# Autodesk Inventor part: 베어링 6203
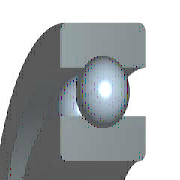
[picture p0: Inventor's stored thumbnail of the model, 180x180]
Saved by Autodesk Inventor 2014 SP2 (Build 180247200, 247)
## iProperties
IsCustomPart: 0
Created: 2018-09
Part Number: 베어링 6203
Material: 스테인리스강
Description: 깊은 그루브 볼 베어링
Document SubType Name: Modeling
Standard: KS B 2023
Standards Organization: KS
Language: ko-KR
Size Designation: 6203 - 17 x 40 x 12
Categories: <MemberInstance><Categories><Category DisplayName="샤프트 부품" InternalName="7f7aeb1f-a693-4053-b835-cee3144e0d98" Mnemonic="SHFT"><Category DisplayName="베어링" Inter
Density: 8.08 g/cm^3
Mass: 66.7997 g
Surface Area: 64.3582 cm^2
Volume: 8.26729 cm^3
Appearance: 보라색
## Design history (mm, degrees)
sketch "스케치" dims "d0" = 5.98 (= -0.26 x WD + 0.26 x BD)
  geometry: L1 (3.01, 14.25)-(8.99, 14.25); L2 (6, 14.25)-(6, 11.26); L3 (6, 14.25)-(6, 17.24); L4 (3.778, 12.249)-(0, 12.249); L5 (0, 8.5)-(12, 8.5); L6 (3.778, 16.251)-(0, 16.251); L7 (0, 20)-(12, 20); L8 (12, 8.5)-(12, 12.249); L9 (8.222, 12.249)-(12, 12.249); L10 (8.222, 16.251)-(12, 16.251); L11 (12, 20)-(12, 16.251); L12 (-1.4, 0)-(8.4, 0) reference; L13 (0, -0.3)-(0, 5.3) reference
  constraints: 22 end point, 4 point on line, 2 collinear, 2 perpendicular, 2 symmetric about line, 1 midpoint, 1 parallel, 14 other
  dimensions: "d9" = 17 diameter of L5 L12 (= WD); "d11" = 40 diameter of L7 L12 (= BD); "d12" = 12 distance between parallel lines of L8 L13 (= KB); "d13" = 24.498 diameter of L9 L12 (= 0.326 x BD + 0.674 x WD)
revolve "본체" stored, may be unused: angle "d6" = 90 deg
revolve "볼" stored, may be unused: angle "d7" = 90 deg
pattern_circular "IDS_ARRAYBALL[SIMPL:T]" dims angle "d3" = 360 deg
body "Solid1"
fillet "모깎기1" dims "d1" = 0.6 (= KRS)
other parameters: "WD" = 17 [user parameter; used in 5 equation terms], "BD" = 40 [user parameter; used in 5 equation terms], "KB" = 12 [user parameter; used in 1 equation term], "KRS" = 0.6 [user parameter; used in 1 equation term], "d4" = 0, "d5" = 0, "d8" = 0, "d14" = 0, "d15" = 0, "BBA" = 0 [user parameter], "BC0" = 4750000 [user parameter], "BC" = 9560000 [user parameter], "WR" = 8.5 (= 0.5 x WD) [user parameter]
